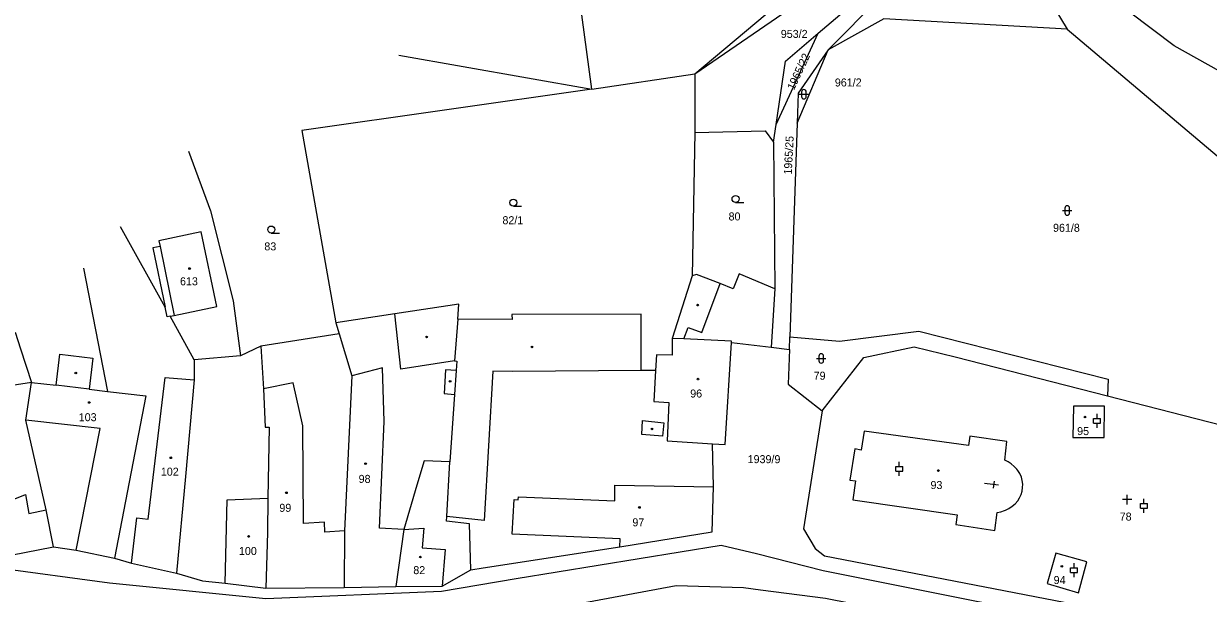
# Model space of a CAD drawing. Extents: x -793666 to -785424, y -1118958 to -1108761.
# Drawn here: x -788273.7 to -788022.1, y -1116375.1 to -1116254.2 of the extents above; entities that cross this region are included whole.
import ezdxf

# ---------------------------------------------------------------- set-up
doc = ezdxf.new("R2010")
doc.units = 0
for name, color, linetype in [('Hranice parcel', 7, 'Continuous'), ('Parcelní čísla', 7, 'Continuous'), ('Vnitřní kresba', 7, 'Continuous'), ('Značky budov', 7, 'Continuous'), ('Značky kultur', 7, 'Continuous')]:
    doc.layers.add(name, color=color, linetype=linetype)

msp = doc.modelspace()

# ---------------------------------------------------------------- linework, layer by layer
at = {"layer": 'Hranice parcel'}
for p, q in [((-788131.17, -1116264.83), (-788085.81, -1116226.64)), ((-788153.05, -1116268.07), (-788156.81, -1116239.54)), ((-788131.17, -1116264.83), (-788091.96, -1116237.85)), ((-788102.81, -1116259.69), (-788091.13, -1116247.9)), ((-788104.94, -1116256.19), (-788099.45, -1116251.52)), ((-788055.15, -1116250.34), (-788052.1, -1116255.33)), ((-788113.88, -1116275.59), (-788104.94, -1116256.19)), ((-788109.43, -1116275.32), (-788102.81, -1116259.69)), ((-788193.99, -1116260.86), (-788153.05, -1116268.07)), ((-788153.05, -1116268.07), (-788131.17, -1116264.83)), ((-788131.17, -1116264.83), (-788131.16, -1116277.26)), ((-788153.05, -1116268.07), (-788214.62, -1116276.87)), ((-788214.62, -1116276.87), (-788207.41, -1116317.68)), ((-788131.16, -1116277.26), (-788131.71, -1116307.69)), ((-788114.43, -1116279.33), (-788113.88, -1116275.59)), ((-788109.43, -1116275.32), (-788110.98, -1116320.69)), ((-788114.43, -1116279.33), (-788114.17, -1116310.48)), ((-788243.66, -1116314.39), (-788253.13, -1116297.29)), ((-788114.17, -1116310.48), (-788114.92, -1116322.89)), ((-788237.48, -1116325.55), (-788242.6, -1116316.31)), ((-788207.41, -1116317.68), (-788206.71, -1116320.02)), ((-788206.71, -1116320.02), (-788223.3, -1116322.65)), ((-788223.3, -1116322.65), (-788227.64, -1116324.73)), ((-788111.07, -1116323.34), (-788110.98, -1116320.69)), ((-788227.64, -1116324.73), (-788237.48, -1116325.55)), ((-788114.92, -1116322.89), (-788111.07, -1116323.34)), ((-788043.51, -1116333.19), (-788015.56, -1116340.35)), ((-788222.28, -1116374.04), (-788205.6, -1116373.91)), ((-788205.6, -1116373.91), (-788194.63, -1116373.69))]:
    msp.add_line(p, q, dxfattribs=at)
for points in [[(-787853.4, -1116319.28), (-787937.67, -1116297.07), (-787968.58, -1116287.61), (-788000.45, -1116274.98), (-788029.34, -1116258.85), (-788038.84, -1116251.72)], [(-788052.1, -1116255.33), (-788091.02, -1116253.11), (-788102.81, -1116259.69)], [(-788113.88, -1116275.59), (-788111.89, -1116262.1), (-788104.94, -1116256.19)], [(-788052.1, -1116255.33), (-788014.79, -1116286.8), (-787989.53, -1116299.12), (-787922.43, -1116312.01), (-787895.37, -1116318.13)], [(-788102.81, -1116259.69), (-788109.21, -1116268.89), (-788109.43, -1116275.32)], [(-788131.16, -1116277.26), (-788116.23, -1116276.92), (-788114.43, -1116279.33)], [(-788238.67, -1116281.26), (-788234.05, -1116293.9), (-788229.21, -1116313.05), (-788227.64, -1116324.73)], [(-788242.6, -1116316.31), (-788241.71, -1116316.13), (-788232.65, -1116314.25), (-788235.99, -1116298.39), (-788244.97, -1116300.29), (-788244.74, -1116301.45), (-788246.29, -1116301.77), (-788243.66, -1116314.39)], [(-788260.98, -1116306.07), (-788255.87, -1116332.24), (-788247.79, -1116333.18), (-788254.43, -1116367.63)], [(-788114.17, -1116310.48), (-788121.75, -1116307.28), (-788123.04, -1116310.44), (-788125.79, -1116309.36), (-788130.81, -1116307.4), (-788131.71, -1116307.69)], [(-788131.71, -1116307.69), (-788135.94, -1116321), (-788135.99, -1116324.59), (-788139.33, -1116324.46), (-788139.53, -1116327.84)], [(-788242.6, -1116316.31), (-788243.23, -1116316.44), (-788243.66, -1116314.39)], [(-788181.52, -1116316.94), (-788181.29, -1116313.7), (-788194.86, -1116315.77), (-788207.41, -1116317.68)], [(-788181.52, -1116316.94), (-788182.17, -1116325.75), (-788181.73, -1116325.82), (-788181.87, -1116327.84), (-788182.21, -1116332.88), (-788183.18, -1116347.24)], [(-788139.53, -1116327.84), (-788142.54, -1116327.81), (-788142.59, -1116315.86), (-788169.99, -1116315.9), (-788169.98, -1116316.98), (-788181.52, -1116316.94)], [(-788275.5, -1116319.65), (-788274.35, -1116323.18), (-788272.01, -1116330.34)], [(-788206.71, -1116320.02), (-788204, -1116328.92), (-788205.54, -1116361.89), (-788205.6, -1116373.91)], [(-788110.98, -1116320.69), (-788100.4, -1116321.61), (-788083.57, -1116319.47), (-788043.34, -1116329.62), (-788043.51, -1116333.19)], [(-788223.3, -1116322.65), (-788222.79, -1116331.74), (-788222.43, -1116339.86), (-788221.57, -1116339.83), (-788221.82, -1116354.94), (-788221.95, -1116362.18), (-788222.28, -1116374.04)], [(-788127.43, -1116343.38), (-788124.74, -1116343.55), (-788123.4, -1116321.9), (-788114.92, -1116322.89)], [(-788111.07, -1116323.34), (-788111.32, -1116330.72), (-788104.08, -1116336.38)], [(-788104.08, -1116336.38), (-788095.27, -1116325.08), (-788084.6, -1116322.77), (-788075.84, -1116324.92), (-788043.51, -1116333.19)], [(-788237.48, -1116325.55), (-788237.49, -1116329.83), (-788239.3, -1116350.35), (-788241.26, -1116370.84)], [(-788139.53, -1116327.84), (-788139.9, -1116334.41), (-788136.65, -1116334.6), (-788137.01, -1116342.78), (-788127.43, -1116343.38)], [(-788272.01, -1116330.34), (-788284.04, -1116332.23), (-788285.35, -1116332.67), (-788280.97, -1116345.92), (-788288.3, -1116348.55)], [(-788267.36, -1116365.28), (-788268.91, -1116357.42), (-788273.24, -1116338.39), (-788272.01, -1116330.34)], [(-788104.08, -1116336.38), (-788108.05, -1116361.45), (-788105.63, -1116365.59), (-788103.61, -1116367.18), (-788046.1, -1116378.3), (-788038.81, -1116378.46), (-788035.35, -1116378.54), (-788022.85, -1116378.83), (-788020.59, -1116378.86)], [(-788044.2, -1116342.07), (-788044.15, -1116335.4), (-788050.76, -1116335.38), (-788050.87, -1116342.02), (-788044.2, -1116342.07)], [(-788065.34, -1116346.88), (-788064.86, -1116342.89), (-788072.76, -1116341.74), (-788073.06, -1116343.77), (-788095.19, -1116340.68), (-788095.84, -1116344.71), (-788097.16, -1116344.45), (-788098.21, -1116351.08), (-788097, -1116351.26), (-788097.58, -1116355.3), (-788075.44, -1116358.49), (-788075.73, -1116360.48), (-788067.47, -1116361.8), (-788066.97, -1116357.98)], [(-788178.72, -1116370.15), (-788176.14, -1116369.75), (-788147.1, -1116365.24), (-788127.46, -1116362.08), (-788127.18, -1116352.49), (-788127.43, -1116343.38)], [(-788183.18, -1116347.24), (-788188.64, -1116346.96), (-788190.2, -1116352.14), (-788192.99, -1116361.57), (-788194.63, -1116373.69)], [(-788178.72, -1116370.15), (-788179.03, -1116360.37), (-788183.89, -1116359.83), (-788183.83, -1116358.84), (-788183.18, -1116347.24)], [(-788066.97, -1116357.98), (-788066.16, -1116357.82), (-788065.37, -1116357.56), (-788065.18, -1116357.48), (-788064.44, -1116357.1), (-788063.75, -1116356.64), (-788063.13, -1116356.1), (-788062.57, -1116355.49), (-788062.18, -1116354.84), (-788061.87, -1116354.15), (-788061.66, -1116353.43), (-788061.54, -1116352.68), (-788061.52, -1116351.92), (-788061.61, -1116351.17), (-788061.79, -1116350.43), (-788062.14, -1116349.71), (-788062.57, -1116349.03), (-788062.78, -1116348.76), (-788063.33, -1116348.17), (-788063.94, -1116347.66), (-788064.62, -1116347.23), (-788065.34, -1116346.88)], [(-788279.68, -1116369.68), (-788255.51, -1116372.91), (-788222.27, -1116376.2), (-788184.96, -1116374.64), (-788169.09, -1116371.97), (-788125.59, -1116364.93), (-788118.03, -1116366.65), (-788103.88, -1116370.26), (-788071.66, -1116376.73), (-788047.19, -1116381.42), (-788037.25, -1116382.67), (-788028.44, -1116382.62), (-788012.56, -1116381.23), (-787982.57, -1116375.12), (-787957.81, -1116369.21), (-787938.9, -1116364.93), (-787918.57, -1116359.78), (-787902.51, -1116353.37)], [(-788280.64, -1116367.02), (-788279.42, -1116367.61), (-788267.36, -1116365.28)], [(-788267.36, -1116365.28), (-788262.56, -1116365.97), (-788254.43, -1116367.63)], [(-788254.43, -1116367.63), (-788250.82, -1116368.7), (-788241.26, -1116370.84)], [(-788054.45, -1116366.61), (-788056.36, -1116373.05), (-788049.67, -1116374.99), (-788047.89, -1116368.42), (-788054.45, -1116366.61)], [(-788194.63, -1116373.69), (-788184.79, -1116373.64), (-788178.72, -1116370.15)], [(-788241.26, -1116370.84), (-788235.7, -1116372.48), (-788230.9, -1116372.95), (-788222.28, -1116374.04)], [(-788014.95, -1116388.89), (-788036.64, -1116389.18), (-788070.79, -1116382.68), (-788103.44, -1116376.2), (-788117.24, -1116374.47), (-788120.83, -1116373.97), (-788135.12, -1116373.51), (-788155.68, -1116377.39), (-788186.34, -1116383.39), (-788190.87, -1116384.17), (-788201.33, -1116384.26), (-788234.5, -1116382.6)]]:
    msp.add_lwpolyline(points, dxfattribs=at)
at = {"layer": 'Vnitřní kresba'}
for p, q in [((-788244.74, -1116301.45), (-788241.71, -1116316.13)), ((-788129.7, -1116319.76), (-788125.79, -1116309.36)), ((-788193.62, -1116327.51), (-788194.86, -1116315.77)), ((-788133.47, -1116321.09), (-788132.56, -1116318.69)), ((-788132.56, -1116318.69), (-788129.7, -1116319.76)), ((-788133.47, -1116321.09), (-788135.94, -1116321)), ((-788123.38, -1116321.58), (-788133.47, -1116321.09)), ((-788123.4, -1116321.9), (-788123.38, -1116321.58)), ((-788266.81, -1116330.95), (-788266.03, -1116324.38)), ((-788266.03, -1116324.38), (-788258.99, -1116325.18)), ((-788258.99, -1116325.18), (-788259.77, -1116331.78)), ((-788197.48, -1116327.27), (-788204, -1116328.92)), ((-788197.15, -1116338.67), (-788197.48, -1116327.27)), ((-788182.17, -1116325.75), (-788193.62, -1116327.51)), ((-788184.08, -1116327.69), (-788184.43, -1116332.73)), ((-788181.87, -1116327.84), (-788184.08, -1116327.69)), ((-788247.25, -1116359.41), (-788243.64, -1116329.31)), ((-788243.64, -1116329.31), (-788237.49, -1116329.83)), ((-788174.03, -1116327.95), (-788175.93, -1116359.64)), ((-788169.82, -1116328.06), (-788174.03, -1116327.95)), ((-788142.54, -1116327.81), (-788169.82, -1116328.06)), ((-788272.01, -1116330.34), (-788266.81, -1116330.95)), ((-788259.77, -1116331.78), (-788266.81, -1116330.95)), ((-788259.77, -1116331.78), (-788255.87, -1116332.24)), ((-788216.44, -1116330.4), (-788222.79, -1116331.74)), ((-788214.44, -1116339.57), (-788216.44, -1116330.4)), ((-788184.43, -1116332.73), (-788182.21, -1116332.88)), ((-788257.49, -1116340.14), (-788273.24, -1116338.39)), ((-788262.56, -1116365.97), (-788257.49, -1116340.14)), ((-788214.27, -1116360.27), (-788214.44, -1116339.57)), ((-788198.15, -1116361.3), (-788197.15, -1116338.67)), ((-788142.41, -1116341.39), (-788142.24, -1116338.46)), ((-788142.24, -1116338.46), (-788137.76, -1116338.96)), ((-788137.76, -1116338.96), (-788138, -1116341.78)), ((-788138, -1116341.78), (-788142.41, -1116341.39)), ((-788148.16, -1116355.5), (-788148.12, -1116352.17)), ((-788148.12, -1116352.17), (-788127.18, -1116352.49)), ((-788276.98, -1116355.65), (-788273.31, -1116354.12)), ((-788273.31, -1116354.12), (-788272.6, -1116358.15)), ((-788230.9, -1116372.95), (-788230.48, -1116355.3)), ((-788230.48, -1116355.3), (-788221.82, -1116354.94)), ((-788169.92, -1116362.58), (-788169.51, -1116355.23)), ((-788169.51, -1116355.23), (-788168.67, -1116355.28)), ((-788168.67, -1116355.28), (-788168.64, -1116354.65)), ((-788168.64, -1116354.65), (-788148.16, -1116355.5)), ((-788272.6, -1116358.15), (-788268.91, -1116357.42)), ((-788250.82, -1116368.7), (-788249.67, -1116359.12)), ((-788249.67, -1116359.12), (-788247.25, -1116359.41)), ((-788209.8, -1116360.02), (-788214.27, -1116360.27)), ((-788209.77, -1116362.11), (-788209.8, -1116360.02)), ((-788175.93, -1116359.64), (-788183.83, -1116358.84)), ((-788205.54, -1116361.89), (-788209.77, -1116362.11)), ((-788192.99, -1116361.57), (-788198.15, -1116361.3)), ((-788192.99, -1116361.57), (-788188.73, -1116361.26)), ((-788188.73, -1116361.26), (-788189.05, -1116365.48)), ((-788147.04, -1116363.56), (-788169.92, -1116362.58)), ((-788189.05, -1116365.48), (-788184.2, -1116365.85)), ((-788147.1, -1116365.24), (-788147.04, -1116363.56)), ((-788184.2, -1116365.85), (-788184.79, -1116373.64))]:
    msp.add_line(p, q, dxfattribs=at)
at = {"layer": 'Značky budov'}
for p, q in [((-788066.67, -1116352.18), (-788069.65, -1116351.81)), ((-788067.58, -1116351.31), (-788067.76, -1116352.8))]:
    msp.add_line(p, q, dxfattribs=at)
for centre in [(-788238.47, -1116306.16), (-788130.57, -1116313.93), (-788188.13, -1116320.69), (-788165.75, -1116322.82), (-788262.64, -1116328.36), (-788183.13, -1116330.1), (-788130.48, -1116329.65), (-788259.79, -1116334.61), (-788048.3, -1116337.7), (-788140.27, -1116340.23), (-788242.45, -1116346.35), (-788201.1, -1116347.61), (-788079.44, -1116349.05), (-788217.89, -1116353.78), (-788142.92, -1116356.9), (-788225.93, -1116363.05), (-788189.45, -1116367.42), (-788053.21, -1116369.41)]:
    msp.add_circle(centre, 0.175, dxfattribs=at)
at = {"layer": 'Značky kultur'}
for p, q in [((-788109, -1116269.16), (-788107, -1116269.16)), ((-788108.5, -1116268.66), (-788108.5, -1116269.66)), ((-788107.5, -1116269.66), (-788107.5, -1116268.66)), ((-788122.51, -1116292.13), (-788120.76, -1116292.13)), ((-788169.7, -1116292.92), (-788167.95, -1116292.92)), ((-788053.07, -1116293.84), (-788051.07, -1116293.84)), ((-788052.57, -1116293.34), (-788052.57, -1116294.34)), ((-788051.57, -1116294.34), (-788051.57, -1116293.34)), ((-788221.12, -1116298.64), (-788219.37, -1116298.64)), ((-788105.31, -1116325.25), (-788103.31, -1116325.25)), ((-788104.81, -1116324.75), (-788104.81, -1116325.75)), ((-788103.81, -1116325.75), (-788103.81, -1116324.75)), ((-788045.73, -1116337.98), (-788045.73, -1116336.98)), ((-788046.48, -1116337.98), (-788044.98, -1116337.98)), ((-788046.48, -1116338.98), (-788046.48, -1116337.98)), ((-788046.48, -1116338.98), (-788044.98, -1116338.98)), ((-788045.73, -1116339.98), (-788045.73, -1116338.98)), ((-788044.98, -1116338.98), (-788044.98, -1116337.98)), ((-788087.74, -1116348.2), (-788087.74, -1116347.2)), ((-788088.49, -1116348.2), (-788086.99, -1116348.2)), ((-788088.49, -1116349.2), (-788088.49, -1116348.2)), ((-788088.49, -1116349.2), (-788086.99, -1116349.2)), ((-788087.74, -1116350.2), (-788087.74, -1116349.2)), ((-788086.99, -1116349.2), (-788086.99, -1116348.2)), ((-788038.34, -1116355.24), (-788040.34, -1116355.24)), ((-788039.34, -1116356.24), (-788039.34, -1116354.24)), ((-788035.76, -1116356.07), (-788035.76, -1116355.07)), ((-788036.51, -1116356.07), (-788035.01, -1116356.07)), ((-788036.51, -1116357.07), (-788036.51, -1116356.07)), ((-788036.51, -1116357.07), (-788035.01, -1116357.07)), ((-788035.76, -1116358.07), (-788035.76, -1116357.07)), ((-788035.01, -1116357.07), (-788035.01, -1116356.07)), ((-788051.35, -1116369.73), (-788049.85, -1116369.73)), ((-788051.35, -1116370.73), (-788051.35, -1116369.73)), ((-788050.6, -1116369.73), (-788050.6, -1116368.73)), ((-788049.85, -1116370.73), (-788049.85, -1116369.73)), ((-788051.35, -1116370.73), (-788049.85, -1116370.73)), ((-788050.6, -1116371.73), (-788050.6, -1116370.73))]:
    msp.add_line(p, q, dxfattribs=at)
for centre in [(-788169.7, -1116292.17), (-788122.51, -1116291.38), (-788221.12, -1116297.89)]:
    msp.add_circle(centre, 0.75, dxfattribs=at)
for centre, start, end in [((-788108, -1116268.66), 0, 180), ((-788108, -1116269.66), 180, 359.9879), ((-788052.07, -1116293.34), 0, 180), ((-788052.07, -1116294.34), 180, 359.9879), ((-788104.31, -1116324.75), 0, 180), ((-788104.31, -1116325.75), 180, 359.9879)]:
    msp.add_arc(centre, 0.5, start, end, dxfattribs=at)

# ---------------------------------------------------------------- texts
at = {"layer": 'Parcelní čísla'}
for s, p in [('953/2', (-788112.9, -1116257.19)), ('961/2', (-788101.42, -1116267.5)), ('82/1', (-788172.02, -1116296.75)), ('80', (-788123.99, -1116295.95)), ('961/8', (-788055.08, -1116298.36)), ('83', (-788222.59, -1116302.31)), ('613', (-788240.5, -1116309.72)), ('79', (-788105.92, -1116329.77)), ('96', (-788132.14, -1116333.55)), ('103', (-788262.01, -1116338.58)), ('95', (-788049.96, -1116341.53)), ('1939/9', (-788119.94, -1116347.49)), ('102', (-788244.57, -1116350.15)), ('98', (-788202.56, -1116351.68)), ('93', (-788081.11, -1116352.99)), ('99', (-788219.4, -1116357.82)), ('78', (-788040.92, -1116359.68)), ('97', (-788144.42, -1116360.9)), ('100', (-788227.98, -1116366.99)), ('82', (-788190.95, -1116371.06)), ('94', (-788054.95, -1116373.16))]:
    msp.add_text(s, height=1.7, dxfattribs=at).set_placement(p)
for s, rotation, p in [('1965/22', 65, (-788110.11, -1116268.41)), ('1965/25', 87, (-788110.58, -1116286.26))]:
    msp.add_text(s, height=1.7, rotation=rotation, dxfattribs=at).set_placement(p)

doc.saveas('drawing.dxf')
